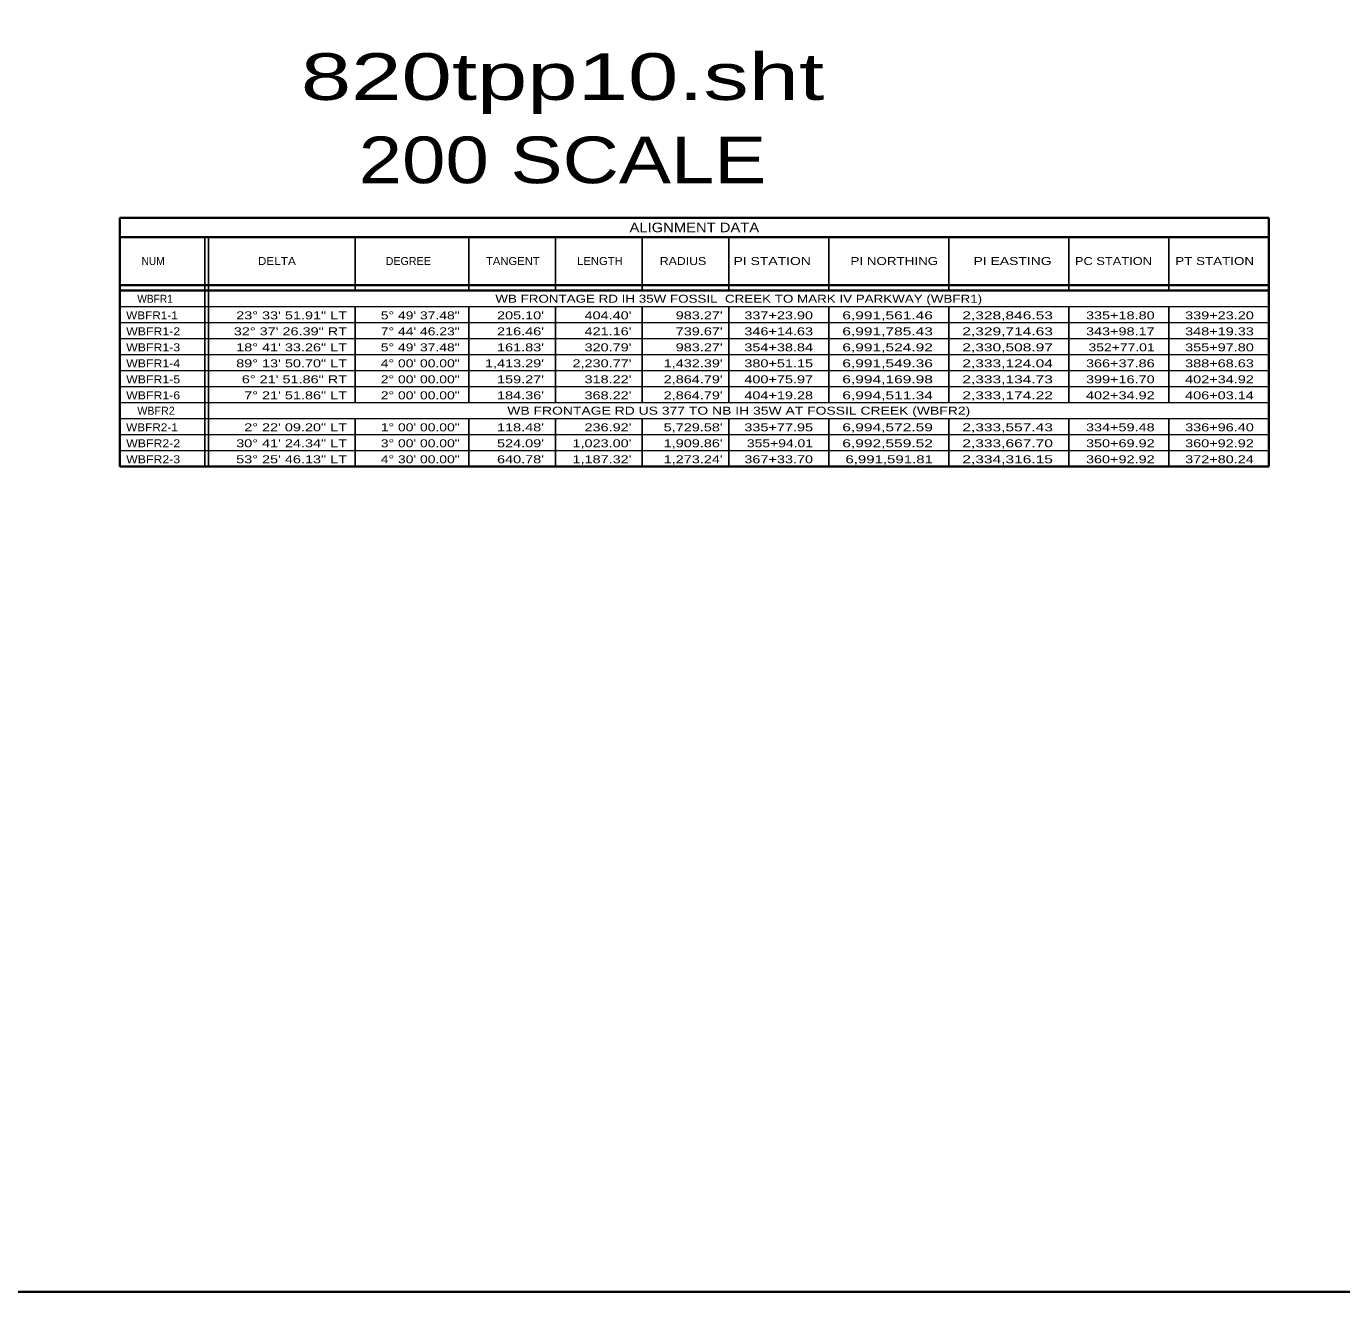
# Model space of a CAD drawing. Extents: x 1953053 to 1967065, y 7363860 to 7371201.
# Drawn here: x 1959817 to 1961790, y 7363860 to 7365759 of the extents above; entities that cross this region are included whole.
import ezdxf
from ezdxf.enums import TextEntityAlignment as Align

# ---------------------------------------------------------------- set-up
doc = ezdxf.new("R2010")
doc.units = 0
doc.header["$LTSCALE"] = 4.8
doc.layers.add('10', color=7, linetype='Continuous')
doc.layers.add('12', color=7, linetype='Continuous', lineweight=25)
doc.layers.add('62', color=7, linetype='Continuous', lineweight=35)

msp = doc.modelspace()

# ---------------------------------------------------------------- linework, layer by layer
at = {"layer": '12', "lineweight": 35}
for p, q in [((1961680.213, 7365471.266), (1959956.881, 7365471.266)), ((1959956.881, 7365471.266), (1959956.881, 7365098.133)), ((1961680.213, 7365098.133), (1961680.213, 7365471.266)), ((1959956.881, 7365442.466), (1961680.213, 7365442.466)), ((1959956.881, 7365370.466), (1961680.213, 7365370.466)), ((1959956.881, 7365362.133), (1961680.213, 7365362.133)), ((1959956.881, 7365098.133), (1961680.213, 7365098.133))]:
    msp.add_line(p, q, dxfattribs=at)
at = {"layer": '12'}
for p, q in [((1960084.726, 7365442.466), (1960084.726, 7365098.133)), ((1960090.213, 7365442.466), (1960090.213, 7365098.133)), ((1960310.213, 7365442.466), (1960310.213, 7365362.133)), ((1960480.213, 7365442.466), (1960480.213, 7365362.133)), ((1960610.213, 7365442.466), (1960610.213, 7365362.133)), ((1960740.213, 7365442.466), (1960740.213, 7365362.133)), ((1960870.213, 7365442.466), (1960870.213, 7365362.133)), ((1961020.213, 7365442.466), (1961020.213, 7365362.133)), ((1961200.213, 7365442.466), (1961200.213, 7365362.133)), ((1961380.213, 7365442.466), (1961380.213, 7365362.133)), ((1961530.213, 7365442.466), (1961530.213, 7365362.133)), ((1960084.726, 7365420.866), (1960084.726, 7365098.133)), ((1960310.213, 7365338.133), (1960310.213, 7365194.133)), ((1960480.213, 7365338.133), (1960480.213, 7365194.133)), ((1960610.213, 7365338.133), (1960610.213, 7365194.133)), ((1960740.213, 7365338.133), (1960740.213, 7365194.133)), ((1960870.213, 7365338.133), (1960870.213, 7365194.133)), ((1961020.213, 7365338.133), (1961020.213, 7365194.133)), ((1961200.213, 7365338.133), (1961200.213, 7365194.133)), ((1961380.213, 7365338.133), (1961380.213, 7365194.133)), ((1961530.213, 7365338.133), (1961530.213, 7365194.133)), ((1960310.213, 7365170.133), (1960310.213, 7365098.133)), ((1960480.213, 7365170.133), (1960480.213, 7365098.133)), ((1960610.213, 7365170.133), (1960610.213, 7365098.133)), ((1960740.213, 7365170.133), (1960740.213, 7365098.133)), ((1960870.213, 7365170.133), (1960870.213, 7365098.133)), ((1961020.213, 7365170.133), (1961020.213, 7365098.133)), ((1961200.213, 7365170.133), (1961200.213, 7365098.133)), ((1961380.213, 7365170.133), (1961380.213, 7365098.133)), ((1961530.213, 7365170.133), (1961530.213, 7365098.133))]:
    msp.add_line(p, q, dxfattribs=at)
at = {"layer": '12', "lineweight": 13}
for p, q in [((1959956.881, 7365338.133), (1961680.213, 7365338.133)), ((1959956.881, 7365314.133), (1961680.213, 7365314.133)), ((1959956.881, 7365290.133), (1961680.213, 7365290.133)), ((1959956.881, 7365266.133), (1961680.213, 7365266.133)), ((1959956.881, 7365242.133), (1961680.213, 7365242.133)), ((1959956.881, 7365218.133), (1961680.213, 7365218.133)), ((1959956.881, 7365194.133), (1961680.213, 7365194.133)), ((1959956.881, 7365170.133), (1961680.213, 7365170.133)), ((1959956.881, 7365146.133), (1961680.213, 7365146.133)), ((1959956.881, 7365122.133), (1961680.213, 7365122.133))]:
    msp.add_line(p, q, dxfattribs=at)
at = {"layer": '62'}
msp.add_lwpolyline([(1953052.784, 7371201.108), (1967065.314, 7371201.108), (1967065.314, 7363859.877), (1953052.784, 7363859.877)], close=True, dxfattribs=at)

# ---------------------------------------------------------------- texts
at = {"layer": '10'}
for s, width, p in [('WBFR1', 0.95, (1959983.154, 7365343.83)), ('WBFR1-1', 1.1, (1959966.502, 7365318.96)), ('WBFR1-2', 1.15, (1959966.502, 7365294.96)), ('WBFR1-3', 1.15, (1959966.502, 7365270.96)), ('WBFR1-4', 1.15, (1959966.502, 7365246.96)), ('WBFR1-5', 1.15, (1959966.502, 7365222.96)), ('WBFR1-6', 1.15, (1959966.502, 7365198.96)), ('WBFR2-1', 1.1, (1959966.502, 7365150.96)), ('WBFR2-2', 1.15, (1959966.502, 7365126.96)), ('WBFR2-3', 1.15, (1959966.502, 7365102.96))]:
    msp.add_text(s, height=12, dxfattribs=dict(at, width=width)).set_placement(p)
for s, width, p in [('WB FRONTAGE RD IH 35W FOSSIL  CREEK TO MARK IV PARKWAY (WBFR1)', 1.25, (1960885.213, 7365343.927)), ('WB FRONTAGE RD US 377 TO NB IH 35W AT FOSSIL CREEK (WBFR2)', 1.3, (1960885.213, 7365175.927))]:
    msp.add_text(s, height=12, dxfattribs=dict(at, width=width)).set_placement(p, align=Align.CENTER)
for s, width, p in [('23° 33\' 51.91" LT', 1.35, (1960297.735, 7365318.96)), ('5° 49\' 37.48"', 1.3, (1960466.73, 7365318.96)), ("205.10'", 1.35, (1960593.14, 7365318.96)), ("404.40'", 1.35, (1960724.337, 7365318.96)), ("983.27'", 1.35, (1960861.106, 7365318.96)), ('337+23.90', 1.35, (1960996.65, 7365318.96)), ('6,991,561.46', 1.45, (1961176.415, 7365318.96)), ('2,328,846.53', 1.45, (1961356.415, 7365318.96)), ('335+18.80', 1.35, (1961508.993, 7365318.96)), ('339+23.20', 1.35, (1961657.725, 7365318.96)), ('32° 37\' 26.39" RT', 1.35, (1960297.735, 7365294.96)), ('7° 44\' 46.23"', 1.3, (1960466.73, 7365294.96)), ("216.46'", 1.35, (1960593.14, 7365294.96)), ("421.16'", 1.35, (1960724.337, 7365294.96)), ("739.67'", 1.35, (1960861.106, 7365294.96)), ('346+14.63', 1.35, (1960996.65, 7365294.96)), ('6,991,785.43', 1.45, (1961176.415, 7365294.96)), ('2,329,714.63', 1.45, (1961356.415, 7365294.96)), ('343+98.17', 1.35, (1961508.993, 7365294.96)), ('348+19.33', 1.35, (1961657.725, 7365294.96)), ('18° 41\' 33.26" LT', 1.35, (1960297.735, 7365270.96)), ('5° 49\' 37.48"', 1.3, (1960466.73, 7365270.96)), ("161.83'", 1.35, (1960593.14, 7365270.96)), ("320.79'", 1.35, (1960724.337, 7365270.96)), ("983.27'", 1.35, (1960861.106, 7365270.96)), ('354+38.84', 1.35, (1960996.65, 7365270.96)), ('6,991,524.92', 1.45, (1961176.415, 7365270.96)), ('2,330,508.97', 1.45, (1961356.415, 7365270.96)), ('352+77.01', 1.3, (1961508.993, 7365270.96)), ('355+97.80', 1.35, (1961657.725, 7365270.96)), ('89° 13\' 50.70" LT', 1.35, (1960297.735, 7365246.96)), ('4° 00\' 00.00"', 1.3, (1960466.73, 7365246.96)), ("1,413.29'", 1.35, (1960593.14, 7365246.96)), ("2,230.77'", 1.35, (1960724.337, 7365246.96)), ("1,432.39'", 1.35, (1960861.106, 7365246.96)), ('380+51.15', 1.35, (1960996.65, 7365246.96)), ('6,991,549.36', 1.45, (1961176.415, 7365246.96)), ('2,333,124.04', 1.45, (1961356.415, 7365246.96)), ('366+37.86', 1.35, (1961508.993, 7365246.96)), ('388+68.63', 1.35, (1961657.725, 7365246.96)), ('6° 21\' 51.86" RT', 1.35, (1960297.735, 7365222.96)), ('2° 00\' 00.00"', 1.3, (1960466.73, 7365222.96)), ("159.27'", 1.35, (1960593.14, 7365222.96)), ("318.22'", 1.35, (1960724.337, 7365222.96)), ("2,864.79'", 1.35, (1960861.106, 7365222.96)), ('400+75.97', 1.35, (1960996.65, 7365222.96)), ('6,994,169.98', 1.45, (1961176.415, 7365222.96)), ('2,333,134.73', 1.45, (1961356.415, 7365222.96)), ('399+16.70', 1.35, (1961508.993, 7365222.96)), ('402+34.92', 1.35, (1961657.725, 7365222.96)), ('7° 21\' 51.86" LT', 1.35, (1960297.735, 7365198.96)), ('2° 00\' 00.00"', 1.3, (1960466.73, 7365198.96)), ("184.36'", 1.35, (1960593.14, 7365198.96)), ("368.22'", 1.35, (1960724.337, 7365198.96)), ("2,864.79'", 1.35, (1960861.106, 7365198.96)), ('404+19.28', 1.35, (1960996.65, 7365198.96)), ('6,994,511.34', 1.45, (1961176.415, 7365198.96)), ('2,333,174.22', 1.45, (1961356.415, 7365198.96)), ('402+34.92', 1.35, (1961508.993, 7365198.96)), ('406+03.14', 1.35, (1961657.725, 7365198.96)), ('2° 22\' 09.20" LT', 1.35, (1960297.735, 7365150.96)), ('1° 00\' 00.00"', 1.3, (1960466.73, 7365150.96)), ("118.48'", 1.35, (1960593.14, 7365150.96)), ("236.92'", 1.35, (1960724.337, 7365150.96)), ("5,729.58'", 1.35, (1960861.106, 7365150.96)), ('335+77.95', 1.35, (1960996.65, 7365150.96)), ('6,994,572.59', 1.45, (1961176.415, 7365150.96)), ('2,333,557.43', 1.45, (1961356.415, 7365150.96)), ('334+59.48', 1.35, (1961508.993, 7365150.96)), ('336+96.40', 1.35, (1961657.725, 7365150.96)), ('30° 41\' 24.34" LT', 1.35, (1960297.735, 7365126.96)), ('3° 00\' 00.00"', 1.3, (1960466.73, 7365126.96)), ("524.09'", 1.35, (1960593.14, 7365126.96)), ("1,023.00'", 1.35, (1960724.337, 7365126.96)), ("1,909.86'", 1.35, (1960861.106, 7365126.96)), ('355+94.01', 1.3, (1960996.65, 7365126.96)), ('6,992,559.52', 1.45, (1961176.415, 7365126.96)), ('2,333,667.70', 1.45, (1961356.415, 7365126.96)), ('350+69.92', 1.35, (1961508.993, 7365126.96)), ('360+92.92', 1.35, (1961657.725, 7365126.96)), ('53° 25\' 46.13" LT', 1.35, (1960297.735, 7365102.96)), ('4° 30\' 00.00"', 1.3, (1960466.73, 7365102.96)), ("640.78'", 1.35, (1960593.14, 7365102.96)), ("1,187.32'", 1.35, (1960724.337, 7365102.96)), ("1,273.24'", 1.35, (1960861.106, 7365102.96)), ('367+33.70', 1.35, (1960996.65, 7365102.96)), ('6,991,591.81', 1.4, (1961176.415, 7365102.96)), ('2,334,316.15', 1.45, (1961356.415, 7365102.96)), ('360+92.92', 1.35, (1961508.993, 7365102.96)), ('372+80.24', 1.35, (1961657.725, 7365102.96))]:
    msp.add_text(s, height=12, dxfattribs=dict(at, width=width)).set_placement(p, align=Align.RIGHT)
msp.add_text('WBFR2', height=12, dxfattribs=at).set_placement((1959983.154, 7365175.83))
at = {"layer": '12'}
for s, height, width, p in [('ALIGNMENT DATA', 14.4, 1.15, (1960818.654, 7365449.665)), ('NUM', 12, 0.95, (1960006.927, 7365400.462)), ('DELTA', 12, 1.1, (1960192.504, 7365400.465)), ('TANGENT', 12, 1.05, (1960546.401, 7365400.465)), ('LENGTH', 12, 1.05, (1960677.036, 7365400.465)), ('RADIUS', 12, 1.15, (1960801.646, 7365400.465)), ('PI STATION', 12, 1.3, (1960935.45, 7365400.465)), ('PI NORTHING', 12, 1.25, (1961118.525, 7365400.465)), ('PI EASTING', 12, 1.3, (1961295.917, 7365400.465)), ('PC STATION', 12, 1.2, (1961447.222, 7365400.465)), ('PT STATION', 12, 1.25, (1961598.993, 7365400.465))]:
    msp.add_text(s, height=height, dxfattribs=dict(at, width=width)).set_placement(p, align=Align.CENTER)
msp.add_text('DEGREE', height=12, dxfattribs=at).set_placement((1960389.59, 7365400.465), align=Align.CENTER)
at = {"layer": '62'}
for s, width, p in [('820tpp10.sht', 1.45, (1960620.937, 7365648.265)), ('200 SCALE', 1.25, (1960620.937, 7365523.265))]:
    msp.add_text(s, height=70, dxfattribs=dict(at, width=width)).set_placement(p, align=Align.CENTER)

doc.saveas('drawing.dxf')
